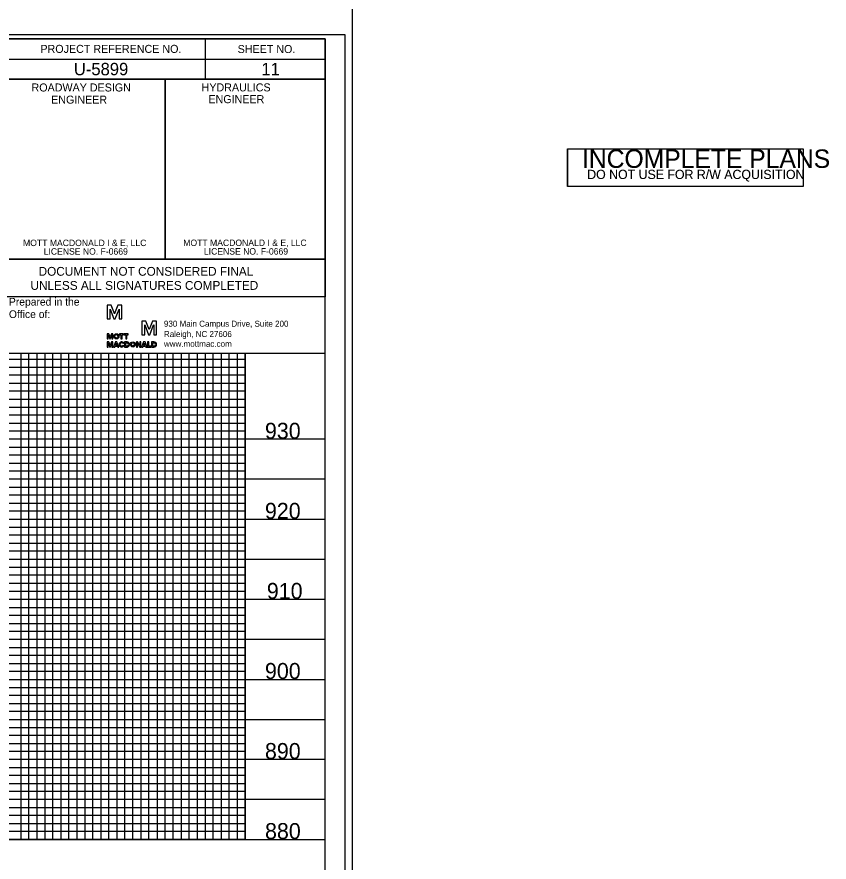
# Model space of a CAD drawing. Extents: x 1967929 to 1975641, y 546296 to 568534.
# Drawn here: x 1971339 to 1971846, y 564695 to 565223 of the extents above; entities that cross this region are included whole.
import ezdxf

# ---------------------------------------------------------------- set-up
doc = ezdxf.new("R2010")
doc.units = 0
for name, color, linetype in [('Exist Vertical Profile Vertical Axis Label', 7, 'Continuous'), ('Old_Level_2', 7, 'Continuous'), ('Old_Level_45', 7, 'Continuous'), ('Scratch_Level_1', 7, 'Continuous'), ('Scratch_Level_3', 7, 'Continuous'), ('Sheet Plot Border Inside CELL', 7, 'Continuous'), ('Sheet Plot Border Outside CELL', 7, 'Continuous'), ('Sheet Profile CELL', 7, 'Continuous'), ('Sheet Profile Grid Major CELL', 7, 'Continuous'), ('Sheet Profile Grid Middle CELL', 7, 'Continuous'), ('Sheet Profile Grid Minor CELL', 7, 'Continuous'), ('Sheet Sticker Incomplete CELL', 7, 'Continuous')]:
    doc.layers.add(name, color=color, linetype=linetype)

msp = doc.modelspace()

# ---------------------------------------------------------------- linework, layer by layer
at = {"layer": 'Old_Level_2'}
for p, q in [((1971397.84, 565042.55), (1971395.31, 565042.55)), ((1971395.31, 565042.55), (1971395.31, 565034.05)), ((1971397.11, 565034.05), (1971397.11, 565040.16)), ((1971397.11, 565040.16), (1971397.13, 565040.16)), ((1971397.13, 565040.16), (1971399.52, 565034.05)), ((1971399.89, 565037.3), (1971397.84, 565042.55)), ((1971401.99, 565042.55), (1971399.94, 565037.3)), ((1971400.3, 565034.05), (1971402.7, 565040.19)), ((1971404.52, 565042.55), (1971401.99, 565042.55)), ((1971402.7, 565040.19), (1971402.72, 565040.19)), ((1971402.72, 565040.19), (1971402.72, 565034.05)), ((1971404.52, 565034.05), (1971404.52, 565042.55)), ((1971399.89, 565037.22), (1971399.89, 565037.3)), ((1971399.94, 565037.22), (1971399.89, 565037.22)), ((1971399.94, 565037.3), (1971399.94, 565037.22)), ((1971395.31, 565034.05), (1971397.11, 565034.05)), ((1971399.52, 565034.05), (1971400.3, 565034.05)), ((1971402.72, 565034.05), (1971404.52, 565034.05)), ((1971419.45, 565032.65), (1971416.93, 565032.65)), ((1971416.93, 565032.65), (1971416.93, 565024.15)), ((1971418.72, 565024.15), (1971418.72, 565030.26)), ((1971418.72, 565030.26), (1971418.75, 565030.26)), ((1971418.75, 565030.26), (1971421.14, 565024.15)), ((1971421.5, 565027.4), (1971419.45, 565032.65)), ((1971423.61, 565032.65), (1971421.56, 565027.4)), ((1971421.92, 565024.15), (1971424.31, 565030.28)), ((1971426.13, 565032.65), (1971423.61, 565032.65)), ((1971424.31, 565030.28), (1971424.34, 565030.28)), ((1971424.34, 565030.28), (1971424.34, 565024.15)), ((1971426.13, 565024.15), (1971426.13, 565032.65)), ((1971396.28, 565024.74), (1971395.31, 565024.74)), ((1971395.31, 565024.74), (1971395.31, 565021.5)), ((1971397.08, 565022.72), (1971396.28, 565024.74)), ((1971397.89, 565024.74), (1971397.08, 565022.72)), ((1971398.85, 565024.74), (1971397.89, 565024.74)), ((1971398.85, 565021.5), (1971398.85, 565024.74)), ((1971408.54, 565024.5), (1971408.56, 565024.5)), ((1971416.93, 565024.15), (1971418.72, 565024.15)), ((1971421.14, 565024.15), (1971421.92, 565024.15)), ((1971421.5, 565027.32), (1971421.5, 565027.4)), ((1971421.56, 565027.32), (1971421.5, 565027.32)), ((1971421.56, 565027.4), (1971421.56, 565027.32)), ((1971424.34, 565024.15), (1971426.13, 565024.15)), ((1971395.31, 565021.5), (1971395.99, 565021.5)), ((1971396.28, 565019.7), (1971395.31, 565019.7)), ((1971395.31, 565019.7), (1971395.31, 565016.45)), ((1971395.99, 565021.5), (1971395.99, 565023.84)), ((1971395.99, 565023.84), (1971396.02, 565023.84)), ((1971396.02, 565023.84), (1971396.93, 565021.5)), ((1971397.08, 565017.67), (1971396.28, 565019.7)), ((1971396.93, 565021.5), (1971397.24, 565021.5)), ((1971397.89, 565019.7), (1971397.08, 565017.67)), ((1971397.24, 565021.5), (1971398.15, 565023.84)), ((1971398.85, 565019.7), (1971397.89, 565019.7)), ((1971398.15, 565023.84), (1971398.17, 565023.84)), ((1971398.15, 565023.84), (1971398.17, 565023.84)), ((1971398.17, 565023.84), (1971398.17, 565021.5)), ((1971398.17, 565021.5), (1971398.85, 565021.5)), ((1971398.85, 565016.45), (1971398.85, 565019.7)), ((1971405.19, 565018.64), (1971405.76, 565018.9)), ((1971407.69, 565019.7), (1971406.2, 565019.7)), ((1971406.2, 565019.7), (1971406.2, 565018.02)), ((1971406.88, 565017.08), (1971406.88, 565019.1)), ((1971406.88, 565019.1), (1971407.69, 565019.1)), ((1971423.02, 565019.7), (1971423.02, 565019.7)), ((1971424.51, 565019.7), (1971423.02, 565019.7)), ((1971423.02, 565019.7), (1971423.02, 565018.02)), ((1971423.7, 565017.08), (1971423.7, 565019.1)), ((1971423.7, 565019.1), (1971424.51, 565019.1)), ((1971424.51, 565019.08), (1971424.51, 565019.08)), ((1971395.31, 565016.45), (1971395.99, 565016.45)), ((1971395.99, 565016.45), (1971395.99, 565018.79)), ((1971395.99, 565018.79), (1971396.02, 565018.79)), ((1971396.02, 565018.79), (1971396.93, 565016.45)), ((1971396.93, 565016.45), (1971397.24, 565016.45)), ((1971397.24, 565016.45), (1971398.15, 565018.79)), ((1971398.15, 565018.79), (1971398.17, 565018.79)), ((1971398.17, 565018.79), (1971398.17, 565016.45)), ((1971398.17, 565016.45), (1971398.85, 565016.45)), ((1971405.67, 565017.12), (1971405.11, 565017.4)), ((1971406.2, 565018.02), (1971406.2, 565016.45)), ((1971406.2, 565016.45), (1971407.69, 565016.45)), ((1971407.69, 565017.08), (1971406.88, 565017.08)), ((1971423.02, 565018.02), (1971423.02, 565016.45)), ((1971423.02, 565016.45), (1971424.51, 565016.45)), ((1971424.51, 565017.08), (1971423.7, 565017.08))]:
    msp.add_line(p, q, dxfattribs=at)
for points in [[(1971402.93, 565024.15), (1971403.87, 565024.15), (1971403.87, 565021.5), (1971404.57, 565021.5), (1971404.57, 565024.15), (1971405.5, 565024.15), (1971405.5, 565024.74), (1971402.93, 565024.74), (1971402.93, 565024.15)], [(1971405.92, 565024.15), (1971406.85, 565024.15), (1971406.85, 565021.5), (1971407.56, 565021.5), (1971407.56, 565024.15), (1971408.49, 565024.15), (1971408.49, 565024.74), (1971405.92, 565024.74), (1971405.92, 565024.15)], [(1971399.24, 565016.45), (1971400.02, 565016.45), (1971400.23, 565017), (1971401.63, 565017), (1971401.84, 565016.45), (1971402.59, 565016.45), (1971401.34, 565019.7), (1971400.49, 565019.7), (1971399.24, 565016.45)], [(1971400.41, 565017.6), (1971400.93, 565019), (1971401.45, 565017.6), (1971400.41, 565017.6)], [(1971414.16, 565018.56), (1971414.19, 565018.56), (1971415.75, 565016.45), (1971416.4, 565016.45), (1971416.39, 565019.7), (1971415.72, 565019.7), (1971415.72, 565017.65), (1971414.18, 565019.7), (1971413.51, 565019.7), (1971413.51, 565016.45), (1971414.16, 565016.45), (1971414.16, 565018.56)], [(1971416.81, 565016.45), (1971417.59, 565016.45), (1971417.8, 565017), (1971419.2, 565017), (1971419.41, 565016.45), (1971420.16, 565016.45), (1971418.92, 565019.7), (1971418.06, 565019.7), (1971416.81, 565016.45)], [(1971417.98, 565017.6), (1971418.5, 565019), (1971419.02, 565017.6), (1971417.98, 565017.6)], [(1971422.63, 565016.45), (1971422.63, 565017.03), (1971421.23, 565017.02), (1971421.23, 565019.7), (1971420.55, 565019.7), (1971420.55, 565016.45), (1971422.63, 565016.45)]]:
    msp.add_lwpolyline(points, dxfattribs=at)
msp.add_arc((1971424.51, 565018.08), 1.62, 270, 90, dxfattribs=at)
for centre, major_axis, ratio in [((1971401.06, 565023.12), (0, 1.62), 0.993118), ((1971401.06, 565023.12), (0, 1.06), 0.916103), ((1971411.33, 565018.08), (0, 1.62), 0.993118), ((1971411.33, 565018.08), (0, 1.06), 0.916103)]:
    msp.add_ellipse(centre, major_axis=major_axis, ratio=ratio, dxfattribs=at)
for centre, major_axis, ratio, start_param, end_param in [((1971404.37, 565018.08), (0, 1.62), 0.993118, 5.246647, 10.366427), ((1971404.37, 565018.08), (0, 1.06), 0.916103, 5.276876, 10.296021), ((1971407.69, 565018.08), (0, -1.62), 0.930276, 0, 3.141593), ((1971407.69, 565018.09), (0, -1.01), 0.900832, 0, 3.141593), ((1971424.51, 565018.09), (0, -1.01), 0.900832, 0, 3.141593)]:
    msp.add_ellipse(centre, major_axis=major_axis, ratio=ratio, start_param=start_param, end_param=end_param, dxfattribs=at)
at = {"layer": 'Scratch_Level_1'}
for p, q in [((1971331.4, 565071.31), (1971531.44, 565071.31)), ((1971531.44, 565071.3), (1971531.44, 565047.8)), ((1971531.44, 565047.81), (1971331.4, 565047.81))]:
    msp.add_line(p, q, dxfattribs=at)
at = {"layer": 'Scratch_Level_3'}
for points in [[(1970081.45, 565208.86), (1970081.45, 564708.86), (1971481.45, 564708.86), (1971481.45, 565012.51), (1971331.4, 565012.51), (1971331.4, 565208.86)], [(1971281.45, 565008.86), (1971481.45, 565008.86), (1971481.45, 564708.86), (1971281.45, 564708.86)]]:
    msp.add_lwpolyline(points, close=True, dxfattribs=at)
at = {"layer": 'Sheet Plot Border Inside CELL'}
msp.add_lwpolyline([(1969877.45, 564156.31), (1971543.95, 564156.31), (1971543.95, 565211.41), (1969877.45, 565211.41)], close=True, dxfattribs=at)
at = {"layer": 'Sheet Plot Border Outside CELL'}
msp.add_lwpolyline([(1969864.45, 564133.86), (1971548.45, 564133.86), (1971548.45, 565233.86), (1969864.45, 565233.86)], close=True, dxfattribs=at)
at = {"layer": 'Sheet Profile CELL'}
for p, q in [((1971456.45, 565208.81), (1971456.45, 565183.81)), ((1971331.4, 565196.31), (1971531.45, 565196.31)), ((1971431.45, 565183.81), (1971431.45, 565071.36)), ((1970031.45, 564708.86), (1971531.45, 564708.86))]:
    msp.add_line(p, q, dxfattribs=at)
for points in [[(1971531.45, 565208.86), (1970031.45, 565208.86), (1970031.45, 564158.86), (1971531.45, 564158.86)], [(1971331.4, 565208.86), (1971531.45, 565208.86), (1971531.45, 565183.81), (1971331.4, 565183.81)], [(1971331.4, 565183.81), (1971431.45, 565183.81), (1971431.45, 565071.31), (1971331.4, 565071.31)], [(1971431.45, 565183.81), (1971531.45, 565183.81), (1971531.45, 565071.31), (1971431.45, 565071.31)]]:
    msp.add_lwpolyline(points, close=True, dxfattribs=at)
msp.add_lwpolyline([(1971531.45, 565012.51), (1971331.4, 565012.51), (1971331.4, 565047.81)], dxfattribs=at)
at = {"layer": 'Sheet Profile Grid Major CELL'}
for points in [[(1970581.4, 565008.86), (1971481.4, 565008.86)], [(1971381.4, 565012.51), (1971381.4, 564708.86), (1971431.4, 564708.86), (1971431.4, 565012.51)], [(1971481.4, 565012.51), (1971481.4, 564708.86), (1971531.4, 564708.86)], [(1971381.4, 564977.21), (1971381.4, 564708.86), (1971431.4, 564708.86), (1971431.4, 564977.21)], [(1971481.4, 564977.21), (1971481.4, 564708.86), (1971531.4, 564708.86)], [(1971531.4, 564958.86), (1970581.4, 564958.86)], [(1970581.4, 564908.86), (1971531.4, 564908.86)], [(1971531.4, 564858.86), (1970581.4, 564858.86)], [(1970581.4, 564808.86), (1971531.4, 564808.86)], [(1971531.4, 564758.86), (1970581.4, 564758.86)]]:
    msp.add_lwpolyline(points, dxfattribs=at)
at = {"layer": 'Sheet Profile Grid Middle CELL'}
for points in [[(1971356.4, 565012.51), (1971356.4, 564708.86), (1971406.4, 564708.86), (1971406.4, 565012.51)], [(1971456.4, 565012.51), (1971456.4, 564708.86)], [(1970581.4, 564983.86), (1971481.4, 564983.86)], [(1971356.4, 564977.21), (1971356.4, 564708.86), (1971406.4, 564708.86), (1971406.4, 564977.21)], [(1971456.4, 564977.21), (1971456.4, 564708.86)], [(1971531.4, 564933.86), (1970581.4, 564933.86)], [(1970581.4, 564883.86), (1971531.4, 564883.86)], [(1971531.4, 564833.86), (1970581.4, 564833.86)], [(1970581.4, 564783.86), (1971531.4, 564783.86)], [(1971531.4, 564733.86), (1970581.4, 564733.86)]]:
    msp.add_lwpolyline(points, dxfattribs=at)
at = {"layer": 'Sheet Profile Grid Minor CELL'}
msp.add_line((1970581.4, 564718.86), (1971481.4, 564718.86), dxfattribs=at)
for points in [[(1971341.4, 565012.51), (1971341.4, 564708.86), (1971346.4, 564708.86), (1971346.4, 565012.51)], [(1971351.4, 565012.51), (1971351.4, 564708.86), (1971361.4, 564708.86), (1971361.4, 565012.51)], [(1971366.4, 565012.51), (1971366.4, 564708.86), (1971371.4, 564708.86), (1971371.4, 565012.51)], [(1971376.4, 565012.51), (1971376.4, 564708.86), (1971386.4, 564708.86), (1971386.4, 565012.52)], [(1971391.4, 565012.51), (1971391.4, 564708.86), (1971396.4, 564708.86), (1971396.4, 565012.51)], [(1971401.4, 565012.51), (1971401.4, 564708.86), (1971411.4, 564708.86), (1971411.4, 565012.51)], [(1971416.4, 565012.51), (1971416.4, 564708.86)], [(1971416.4, 564708.86), (1971421.4, 564708.86), (1971421.4, 565012.51)], [(1971426.4, 565012.51), (1971426.4, 564708.86), (1971436.4, 564708.86), (1971436.4, 565012.51)], [(1971441.4, 565012.51), (1971441.4, 564708.86), (1971446.4, 564708.86), (1971446.4, 565012.51)], [(1971451.4, 565012.51), (1971451.4, 564708.86), (1971461.4, 564708.86), (1971461.4, 565012.51)], [(1971466.4, 565012.51), (1971466.4, 564708.86), (1971471.4, 564708.86), (1971471.4, 565012.51)], [(1971476.4, 565012.51), (1971476.4, 564708.86), (1971486.4, 564708.86)], [(1970581.4, 565003.86), (1971481.4, 565003.86)], [(1971481.4, 564998.86), (1970581.4, 564998.86)], [(1970581.4, 564993.86), (1971481.4, 564993.86)], [(1971481.4, 564988.86), (1970581.4, 564988.86)], [(1970581.4, 564978.86), (1971481.4, 564978.86)], [(1971341.4, 564977.21), (1971341.4, 564708.86), (1971346.4, 564708.86), (1971346.4, 564977.21)], [(1971351.4, 564977.21), (1971351.4, 564708.86), (1971361.4, 564708.86), (1971361.4, 564977.21)], [(1971366.4, 564977.21), (1971366.4, 564708.86), (1971371.4, 564708.86), (1971371.4, 564977.21)], [(1971376.4, 564977.21), (1971376.4, 564708.86), (1971386.4, 564708.86), (1971386.4, 564977.21)], [(1971391.4, 564977.21), (1971391.4, 564708.86), (1971396.4, 564708.86), (1971396.4, 564977.21)], [(1971401.4, 564977.21), (1971401.4, 564708.86), (1971411.4, 564708.86), (1971411.4, 564977.21)], [(1971416.4, 564977.21), (1971416.4, 564708.86)], [(1971416.4, 564708.86), (1971421.4, 564708.86), (1971421.4, 564977.21)], [(1971426.4, 564977.21), (1971426.4, 564708.86), (1971436.4, 564708.86), (1971436.4, 564977.21)], [(1971441.4, 564977.21), (1971441.4, 564708.86), (1971446.4, 564708.86), (1971446.4, 564977.21)], [(1971451.4, 564977.21), (1971451.4, 564708.86), (1971461.4, 564708.86), (1971461.4, 564977.21)], [(1971466.4, 564977.21), (1971466.4, 564708.86), (1971471.4, 564708.86), (1971471.4, 564977.21)], [(1971476.4, 564977.21), (1971476.4, 564708.86), (1971486.4, 564708.86)], [(1971481.4, 564973.86), (1970581.4, 564973.86)], [(1970581.4, 564968.86), (1971481.4, 564968.86)], [(1971481.4, 564963.86), (1970581.4, 564963.86)], [(1970581.4, 564953.86), (1971481.4, 564953.86)], [(1971481.4, 564948.86), (1970581.4, 564948.86)], [(1970581.4, 564943.86), (1971481.4, 564943.86)], [(1971481.4, 564938.86), (1970581.4, 564938.86)], [(1970581.4, 564928.86), (1971481.4, 564928.86)], [(1971481.4, 564923.86), (1970581.4, 564923.86)], [(1970581.4, 564918.86), (1971481.4, 564918.86)], [(1971481.4, 564913.86), (1970581.4, 564913.86)], [(1970581.4, 564903.86), (1971481.4, 564903.86)], [(1971481.4, 564898.86), (1970581.4, 564898.86)], [(1970581.4, 564893.86), (1971481.4, 564893.86)], [(1971481.4, 564888.86), (1970581.4, 564888.86)], [(1970581.4, 564878.86), (1971481.4, 564878.86)], [(1971481.4, 564873.86), (1970581.4, 564873.86)], [(1970581.4, 564868.86), (1971481.4, 564868.86)], [(1971481.4, 564863.86), (1970581.4, 564863.86)], [(1970581.4, 564853.86), (1971481.4, 564853.86)], [(1971481.4, 564848.86), (1970581.4, 564848.86)], [(1970581.4, 564843.86), (1971481.4, 564843.86)], [(1971481.4, 564838.86), (1970581.4, 564838.86)], [(1970581.4, 564828.86), (1971481.4, 564828.86)], [(1971481.4, 564823.86), (1970581.4, 564823.86)], [(1970581.4, 564818.86), (1971481.4, 564818.86)], [(1971481.4, 564813.86), (1970581.4, 564813.86)], [(1970581.4, 564803.86), (1971481.4, 564803.86)], [(1971481.4, 564798.86), (1970581.4, 564798.86)], [(1970581.4, 564793.86), (1971481.4, 564793.86)], [(1971481.4, 564788.86), (1970581.4, 564788.86)], [(1970581.4, 564778.86), (1971481.4, 564778.86)], [(1971481.4, 564773.86), (1970581.4, 564773.86)], [(1970581.4, 564768.86), (1971481.4, 564768.86)], [(1971481.4, 564763.86), (1970581.4, 564763.86)], [(1970581.4, 564753.86), (1971481.4, 564753.86)], [(1971481.4, 564748.86), (1970581.4, 564748.86)], [(1970581.4, 564743.86), (1971481.4, 564743.86)], [(1971481.4, 564738.86), (1970581.4, 564738.86)], [(1970581.4, 564728.86), (1971481.4, 564728.86)], [(1971481.4, 564723.86), (1970581.4, 564723.86)], [(1970531.35, 564713.86), (1970081.4, 564713.86), (1970081.4, 564708.86), (1971481.4, 564708.86)], [(1971481.4, 564713.86), (1970581.4, 564713.86)]]:
    msp.add_lwpolyline(points, dxfattribs=at)
at = {"layer": 'Sheet Sticker Incomplete CELL'}
for points in [[(1971682.78, 565116.64), (1971682.78, 565140.14), (1971829.78, 565140.14), (1971829.78, 565116.64)], [(1971682.86, 565116.64), (1971682.86, 565140.14), (1971829.86, 565140.14), (1971829.86, 565116.64)]]:
    msp.add_lwpolyline(points, close=True, dxfattribs=at)

# ---------------------------------------------------------------- texts
at = {"layer": 'Exist Vertical Profile Vertical Axis Label'}
for s, p in [('930', (1971493.79, 564959.11)), ('920', (1971493.79, 564909.11)), ('910', (1971494.99, 564859.11)), ('900', (1971493.79, 564809.11)), ('890', (1971493.79, 564759.11)), ('880', (1971493.84, 564709.11))]:
    msp.add_text(s, height=10, dxfattribs=at).set_placement(p)
at = {"layer": 'Old_Level_2'}
for s, height, p in [('Prepared in the ', 4.8186, (1971333.95, 565042.31)), ('Office of:', 4.819, (1971333.95, 565034.56))]:
    msp.add_text(s, height=height, dxfattribs=at).set_placement(p)
for s, p in [('930 Main Campus Drive, Suite 200', (1971430.73, 565029.13)), ('Raleigh, NC 27606', (1971430.73, 565022.68)), ('www.mottmac.com', (1971430.73, 565016.59))]:
    msp.add_text(s, height=3.75, rotation=360, dxfattribs=at).set_placement(p)
at = {"layer": 'Old_Level_45'}
for s, p in [('MOTT MACDONALD I & E, LLC', (1971342.76, 565079.49)), ('MOTT MACDONALD I & E, LLC', (1971442.81, 565079.54)), (' LICENSE NO. F-0669', (1971354.15, 565074.14)), (' LICENSE NO. F-0669', (1971454.2, 565074.19))]:
    msp.add_text(s, height=4.0179, dxfattribs=at).set_placement(p)
at = {"layer": 'Scratch_Level_1'}
for s, p in [('DOCUMENT NOT CONSIDERED FINAL', (1971352.47, 565060.97)), ('UNLESS ALL SIGNATURES COMPLETED', (1971347.4, 565052.17))]:
    msp.add_text(s, height=5.5, dxfattribs=at).set_placement(p)
at = {"layer": 'Sheet Profile CELL'}
for s, height, p in [('PROJECT REFERENCE NO.', 5.0001, (1971353.6, 565200.16)), ('SHEET NO.', 5, (1971476.75, 565200.06)), ('U-5899', 7.75, (1971374.47, 565186.19)), ('11', 7.75, (1971491.55, 565186.19)), ('ROADWAY DESIGN', 5.0001, (1971348.05, 565176.06)), ('HYDRAULICS', 5, (1971454.25, 565176.11)), ('ENGINEER', 5, (1971360.3, 565168.46)), ('ENGINEER', 5, (1971458.5, 565168.76))]:
    msp.add_text(s, height=height, dxfattribs=at).set_placement(p)
at = {"layer": 'Sheet Sticker Incomplete CELL'}
for s, height, p in [('INCOMPLETE PLANS', 11.52, (1971691.73, 565128.34)), ('INCOMPLETE PLANS', 11.52, (1971691.81, 565128.34)), ('DO NOT USE FOR R/W ACQUISITION', 5.76, (1971694.98, 565121.39)), ('DO NOT USE FOR R/W ACQUISITION', 5.76, (1971695.06, 565121.39))]:
    msp.add_text(s, height=height, dxfattribs=at).set_placement(p)

doc.saveas('drawing.dxf')
